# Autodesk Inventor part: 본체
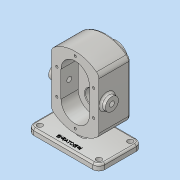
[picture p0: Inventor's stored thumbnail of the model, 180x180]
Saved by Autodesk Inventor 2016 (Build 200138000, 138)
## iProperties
Created: 2019-03
Part Number: 본체
Material: 알루미늄 6061
Document SubType Name: Modeling
Designer: Administrator
Density: 2.7 g/cm^3
Appearance: 알루미늄 - 평지
Mass: 1187.09 g
Surface Area: 719.389 cm^2
Volume: 439.665 cm^3
Author: Administrator
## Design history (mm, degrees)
sketch "스케치1"
  geometry: L1 (-60, 36.5)-(60, 36.5); L2 (60, 36.5)-(60, -36.5); L3 (60, -36.5)-(-60, -36.5); L4 (-60, -36.5)-(-60, 36.5); L5 (-60, 36.5)-(60, -36.5); L6 (60, 36.5)-(-60, -36.5); 1 further point
  constraints: 12 end point, 2 midpoint, 2 parallel, 1 horizontal, 1 perpendicular
  dimensions: "d0" = 120 distance of L2.end L3.end; "d1" = 73 distance of L1.end L2.end
extrude "돌출1" new body sketch "스케치1" distance "d2" = 10; taper "d3" = 0 deg
sketch "스케치4"
  geometry: L1 (0, 0)-(120, 0) reference; L2 (20, -122.721)-(20, -33.279); L3 (100, -33.279)-(100, -122.721); L4 (100, -78)-(20, -78); L5 (60, -138)-(60, -18); L6 (120, 0)-(0, 0) reference; A1 r 60 centre (60, -78) between (20, -122.721) and (100, -122.721); A2 r 60 centre (60, -78) between (100, -33.279) and (20, -33.279); 3 further points
  constraints: 8 end point, 6 point on circle, 4 midpoint, 2 centre point, 2 parallel, 1 vertical, 1 vertical alignment
  dimensions: "d9" = 60 radius of A1; "d10" = 60 radius of A2; "d11" = 80 distance between parallel lines of L2 L3; "d12" = 78 distance between parallel lines of L1 L4; "d13" = 138 dimension on A1 L1
extrude "돌출2" join sketch "스케치4" distance "d14" = 53; taper "d15" = 0 deg
sketch "스케치5"
  geometry: L1 (-6, 36.5)-(6, 36.5); L2 (6, 36.5)-(6, -6.5); L3 (6, -6.5)-(-6, -6.5); L4 (-6, -6.5)-(-6, 36.5); L5 (-60, 36.5)-(60, 36.5) reference; 3 further points
  constraints: 8 end point, 2 midpoint, 2 parallel, 2 vertical alignment, 1 horizontal, 1 perpendicular
  dimensions: "d18" = 43 distance of L1.end L2.end; "d19" = 12 distance of L1.start L1.end; "d20" = 0 distance between parallel lines of L5 L1
extrude "돌출3" join sketch "스케치5" stored distance "d21" = 53; taper "d22" = 0 deg
sketch "스케치7"
  geometry: L1 (20, 122.721)-(20, 33.279) reference; L2 (20, 78)-(100, 78); L3 (100, 33.279)-(100, 122.721) reference; L4 (36, 100)-(36, 56); L5 (84, 100)-(84, 56); A1 r 24 centre (60, 100) between (84, 100) and (36, 100); A2 r 24 centre (60, 56) between (36, 56) and (84, 56); A3 r 60 centre (60, 78) between (100, 122.721) and (20, 122.721) reference; A4 r 60 centre (60, 78) between (20, 33.279) and (100, 33.279) reference; 5 further points
  constraints: 8 point on circle, 6 end point, 2 centre point, 2 midpoint, 2 tangent, 2 vertical alignment, 1 symmetric about line, 1 vertical, 1 other
  dimensions: "d23" = 24 radius of A1; "d24" = 22 distance from line of L2 A1.centre; "d25" = 44 distance of A2.centre A1.centre (derived)
extrude "돌출4" cut sketch "스케치7" distance "d26" = 29; taper "d27" = 0 deg
sketch "스케치8"
  geometry: L1 (36, 56)-(36, 100) reference; L2 (84, 100)-(84, 56) reference; C1 r 12.5 at (60, 100); C2 r 12.5 at (60, 56); A1 r 24 centre (60, 100) between (84, 100) and (36, 100) reference; A2 r 24 centre (60, 56) between (36, 56) and (84, 56) reference; 1 further point
  constraints: 2 centre point, 2 coincident
  dimensions: "d28" = 25 diameter of C1; "d29" = 25 diameter of C2
extrude "돌출5" cut sketch "스케치8" distance "d30" = 15; taper "d31" = 0 deg
sketch "스케치10"
  geometry: L1 (100, -33.279)-(100, -122.721) reference; L2 (100, -78)-(20, -78); L3 (20, -122.721)-(20, -33.279) reference; C1 r 19 at (60, -100); 1 further point
  constraints: 2 end point, 2 midpoint, 1 centre point, 1 vertical alignment
  dimensions: "d32" = 38 diameter of C1; "d33" = 22 distance from line of L2 C1.centre
extrude "돌출6" join sketch "스케치10" distance "d34" = 17; taper "d35" = 0 deg
hole "구멍1" diameter "d38" = 17; stored, may be unused: countersink angle "d42" = 90 deg, drill point angle "d44" = 118 deg; dims "d36" = 10, "d37" = 10, "d39" = 6, "d40" = 28, "d41" = 7.3, "d43" = 8
sketch "스케치11"
  geometry: L1 (60, 100)-(60, 131); L2 (29, 100)-(91, 100); L3 (29, 56)-(91, 56); L4 (60, 56)-(60, 25); C1 r 8.5 at (60, 100) reference; C2 r 12.5 at (60, 56) reference; C3 r 12.5 at (60, 100) reference; A1 r 31 centre (60, 100) between (60, 131) and (29, 100); A2 r 31 centre (60, 56) between (29, 56) and (91, 56); 9 further points
  constraints: 8 coincident, 8 end point, 6 point on circle, 3 horizontal alignment, 2 centre point, 2 horizontal, 2 midpoint, 1 vertical, 1 vertical alignment
  dimensions: "d45" = 31 radius of A1; "d46" = 31 radius of A2
hole "구멍4" sketch "스케치11" at (60, 131), (29, 100), (91, 100), (91, 56), (60, 25), (29, 56) diameter "d61" = 4.134; stored, may be unused: countersink angle "d65" = 90 deg, drill point angle "d67" = 118 deg; dims "d62" = 10, "d63" = 28, "d64" = 7.3, "d66" = 12
fillet "모깎기1" dims "d68" = 10
sketch "스케치12"
  geometry: A1 r 10 centre (-50, 26.5) between (-50, 36.5) and (-60, 26.5) reference; A2 r 10 centre (-50, -26.5) between (-60, -26.5) and (-50, -36.5) reference; A3 r 10 centre (50, -26.5) between (50, -36.5) and (60, -26.5) reference; A4 r 10 centre (50, 26.5) between (60, 26.5) and (50, 36.5) reference; 5 further points
  constraints: 4 coincident
hole "구멍5" sketch "스케치12" at (-50, -26.5), (50, -26.5), (50, 26.5), (-50, 26.5) diameter "d74" = 9; stored, may be unused: countersink angle "d78" = 90 deg, drill point angle "d80" = 118 deg; dims "d75" = 10, "d76" = 28, "d77" = 7.3, "d79" = 12
fillet "모깎기7" dims "d81" = 10
fillet "모깎기8" dims "d82" = 3
fillet "모깎기9" dims "d83" = 3
fillet "모깎기10" dims "d84" = 3
fillet "모깎기11" dims "d85" = 3
fillet "모깎기12" dims "d86" = 3
chamfer "모따기1" distance "d87" = 0.7; stored, may be unused: second distance "d88" = 2, angle "d89" = 30 deg
fillet "모깎기13" dims "d90" = 0.5
sketch "스케치13"
  geometry: L1 (62, 0)-(18, 0) reference; L2 (40, 0)-(40, 50); L3 (80, 50)-(0, 50) reference; C1 r 11 at (40, 14); 1 further point
  constraints: 2 end point, 2 midpoint, 1 centre point, 1 point on line
  dimensions: "d92" = 22 diameter of C1; "d93" = 14 distance from line of L1 C1.centre
extrude "돌출7" join sketch "스케치13" distance "d94" = 8; taper "d95" = 0 deg
hole "구멍6" diameter "d98" = 8.376; stored, may be unused: countersink angle "d102" = 90 deg, drill point angle "d104" = 118 deg; dims "d96" = 10, "d97" = 10, "d99" = 20, "d100" = 28, "d101" = 7.3, "d103" = 27.3
fillet "모깎기14" dims "d105" = 3
chamfer "모따기2" distance "d106" = 1; stored, may be unused: second distance "d107" = 2, angle "d108" = 30 deg
sketch "스케치14"
  geometry: L1 (-50, -36.5)-(50, -36.5) reference; L2 (-60, 26.5)-(-60, -26.5) reference; 2 further points
  constraints: 1 other
  dimensions: "d109" = 10 distance from line of L1 point (0, -26.5); "d110" = 60 distance from line of L2 point (0, -26.5)
feature "엠보싱1" sketch "스케치14" dims "d0" = 120, "d1" = 73, "d111" = 0.5, "d112" = 0
sketch "스케치15"
  geometry: L1 (-46.332, 148.737)-(75.805, 148.737); L2 (75.805, 148.737)-(75.805, 25.352); L3 (75.805, 25.352)-(-46.332, 25.352); L4 (-46.332, 25.352)-(-46.332, 148.737); 1 further point
  constraints: 8 end point, 2 parallel, 1 horizontal, 1 perpendicular
extrude "돌출8" cut sketch "스케치15" stored distance "d113" = 10; taper "d114" = 0 deg
fillet "모깎기15" dims "d115" = 3
node "솔리드1"
mirror "대칭1"
mirror "대칭2"
node "투영된 루프1"
